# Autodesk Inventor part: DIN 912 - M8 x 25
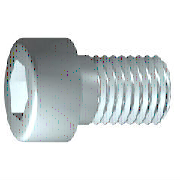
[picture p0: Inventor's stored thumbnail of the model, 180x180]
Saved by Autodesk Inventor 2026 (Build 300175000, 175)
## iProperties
Created: 2021-02
Part Number: DIN 912 - M8 x 25
Material: Silver
Description: Cylinder Head Cap Screw
Document SubType Name: Modeling
Standard: DIN 912
Designer: Lars Bertram Pedersen
Standards Organization: DIN
Language: en-US
Size Designation: M8 x 25
Categories: <MemberInstance><Categories><Category DisplayName="Fasteners" InternalName="e4da775c-781d-43d5-af7c-5136215cf5a6" Mnemonic="FSTN"><Category DisplayName="Bolts"
Density: 10.49 g/cm^3
Appearance: Silver
Mass: 22.6359 g
Surface Area: 12.8152 cm^2
Volume: 2.15785 cm^3
IsCustomPart: 1
Author: Lars Bertram Pedersen
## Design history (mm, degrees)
workplane "Work Plane1"
fillet "Fillet2" dims "d30" = 0.4 (= R)
revolve "Body" stored, may be unused: angle "d10" = 90 deg
sketch "Sketch2"
  geometry: L1 (0, -9.1)-(0, 9.1) reference; L2 (-9.1, 0)-(9.1, 0) reference; L3 (3.464, 0)-(1.732, -3); L4 (1.732, -3)-(-1.732, -3); L5 (-1.732, -3)-(-3.464, 0); L6 (-3.464, 0)-(-1.732, 3); L7 (-1.732, 3)-(1.732, 3); L8 (1.732, 3)-(3.464, 0); 2 further points
  constraints: 12 end point, 1 coincident, 1 horizontal alignment, 1 point on line, 12 other
extrude "Slot" join sketch "Sketch2" stored distance "d11" = 10; taper "d12" = 0 deg
body "Solid1"
fillet "Fillet1" dims "d17" = 0.8 (= RR)
feature "Thread" dims "d13" = 21.875 (= GEL), "d14" = 0
chamfer "Chamfer1" distance "d15" = 0.76681 (= -0.5 x SPD + 0.5 x GD); stored, may be unused: second distance "d16" = 0.76681 (= GUL), angle "d27" = 45 deg
sketch "Sketch1"
  geometry: L1 (-2, 0)-(25, 0); L2 (25, 0)-(25, 4); L3 (25, 4)-(3.125, 4); L4 (3.125, 4)-(2.358, 4); L5 (2.358, 4)-(0, 4); L6 (0, 4)-(0, 6.5); L7 (0, 6.5)-(-8, 6.5); L8 (-8, 6.5)-(-8, 3.464); L9 (-8, 3.464)-(-4, 3.464); L10 (-4, 3.464)-(-2, 0); L11 (-14.6, 0)-(31.6, 0) reference; L12 (0, -1.3)-(0, 7.8) reference; L13 (3.125, 4)-(0, 4)
  constraints: 22 end point, 6 parallel, 2 collinear, 2 perpendicular, 1 horizontal, 1 point on line
  dimensions: "d1" = 21.875 distance from line of L3.end L2 (= GEL); "d2" = 0.76691 distance of L4.end L3.end (computed from GAL); "d3" = 8 distance between parallel lines of L8 L6 (= KOH); "d4" = 4 distance of L8.end L9.end (= INTI); "d5" = 60 deg angle of L10 L1; "d6" = 8 diameter of L3 L1 (= GD); "d7" = 8 diameter of L5 L1 (= BDM); "d8" = 6.9282 diameter of L9 L1 (= 1.1547 x SW); "d9" = 13 diameter of L7 L1 (= KOD); "d26" = 25 distance between parallel lines of L12 L2 (= NLG)
other parameters: "GD" = 8 (= NND) [user parameter; used in 2 equation terms], "NLG" = 25 [user parameter; used in 1 equation term], "GEL" = 21.875 [user parameter; used in 2 equation terms], "KOD" = 13 [user parameter; used in 1 equation term], "KOH" = 8 [user parameter; used in 1 equation term], "INTI" = 4 [user parameter; used in 1 equation term], "GAL" = 0.76681 (= 0.61345 x PTC) [user parameter; used in 1 equation term], "GUL" = 0.76681 (= 0.61345 x PTC) [user parameter; used in 1 equation term], "BDM" = 8 (= NND) [user parameter; used in 1 equation term], "SW" = 6 [user parameter; used in 2 equation terms], "RR" = 0.8 [user parameter; used in 1 equation term], "SPD" = 6.46637 (= NND - 1.2269 x PTC) [user parameter; used in 1 equation term], "d19" = 0, "d28" = 0, "d29" = 0, "R" = 0.4 [user parameter; used in 1 equation term], "TOA" = 30 deg [user parameter], "GD1" = 6.46637 (= THREADDIA - 1.2269 x PTC) [user parameter], "THREADDIA" = 8 [user parameter; used in 1 equation term], "FAWI" = 45 deg [user parameter], "ANG" = 120 deg [user parameter], "TPU" = 8 (computed from PTC) [user parameter], "PTC" = 1.25 [user parameter; used in 5 equation terms], "NND" = 8 [user parameter; used in 3 equation terms], "E0" = 6.93 (= 1.155 x SW) [user parameter]
